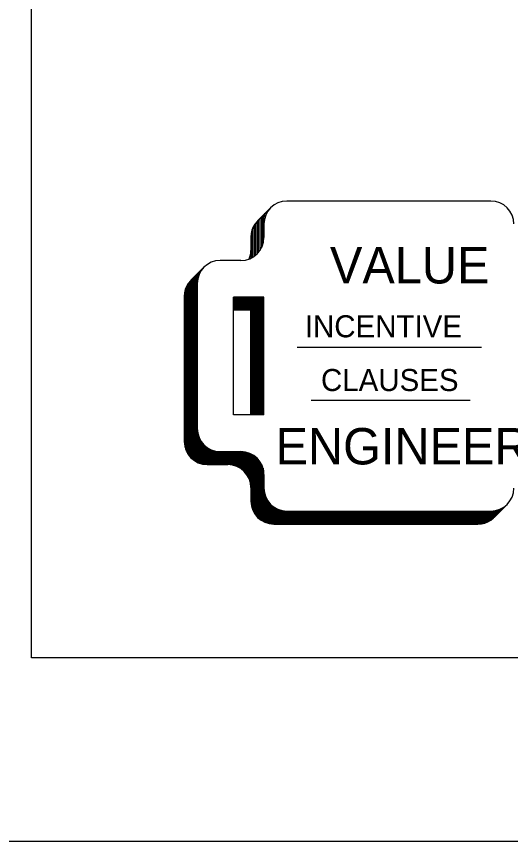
# Model space of a CAD drawing. Extents: x 0 to 53.3, y -2.9 to 37.3.
# Drawn here: x 1.943 to 3.736, y 0.002 to 2.995 of the extents above; entities that cross this region are included whole.
import ezdxf

# ---------------------------------------------------------------- set-up
doc = ezdxf.new("R2010")
doc.units = 0
doc.layers.add('Level 1', color=7, linetype='Continuous')

msp = doc.modelspace()

# ---------------------------------------------------------------- linework, layer by layer
at = {"layer": 'Level 1'}
for p, q in [((3.6651, 2.3253), (2.9244, 2.3253)), ((2.8183, 2.2538), (2.8654, 2.3009)), ((2.8411, 2.2419), (2.8411, 2.2766)), ((2.8451, 2.2674), (2.8451, 2.2806)), ((2.8494, 2.2783), (2.8494, 2.2849)), ((2.8536, 2.2858), (2.8536, 2.2891)), ((2.8571, 2.2911), (2.8571, 2.2926)), ((2.8149, 2.2501), (2.8149, 2.1321)), ((2.8204, 2.2559), (2.8204, 2.1378)), ((2.8261, 2.2616), (2.8261, 2.1451)), ((2.8321, 2.2676), (2.8321, 2.1551)), ((2.8378, 2.2733), (2.8378, 2.1694)), ((2.7984, 2.2218), (2.7984, 2.1201)), ((2.8041, 2.2346), (2.8041, 2.1234)), ((2.8093, 2.2429), (2.8093, 2.1273)), ((2.8411, 2.2419), (2.8411, 2.1928)), ((2.7939, 2.1948), (2.7939, 2.1178)), ((2.7578, 2.1094), (2.6824, 2.1094)), ((2.5763, 2.0379), (2.6234, 2.0851)), ((2.6051, 2.0571), (2.6051, 2.0668)), ((2.6068, 2.0609), (2.6068, 2.0684)), ((2.6083, 2.0641), (2.6083, 2.0699)), ((2.6099, 2.0673), (2.6099, 2.0716)), ((2.6116, 2.0699), (2.6116, 2.0733)), ((2.6133, 2.0726), (2.6133, 2.0749)), ((2.6149, 2.0749), (2.6149, 2.0766)), ((2.5743, 2.0358), (2.5743, 1.3954)), ((2.5766, 2.0381), (2.5766, 1.3931)), ((2.5794, 2.0411), (2.5794, 1.3904)), ((2.5814, 2.0431), (2.5814, 1.3886)), ((2.5836, 2.0453), (2.5836, 1.3869)), ((2.5863, 2.0479), (2.5863, 1.3849)), ((2.5891, 2.0508), (2.5891, 1.3829)), ((2.5914, 2.0531), (2.5914, 1.3814)), ((2.5936, 2.0553), (2.5936, 1.3801)), ((2.5958, 2.0574), (2.5958, 1.3789)), ((2.5973, 2.0589), (2.5973, 1.3781)), ((2.5991, 2.0261), (2.5991, 2.0608)), ((2.6009, 2.0434), (2.6009, 2.0626)), ((2.6033, 2.0521), (2.6033, 2.0649)), ((2.5568, 2.0069), (2.5568, 1.4243)), ((2.5594, 2.0134), (2.5594, 1.4178)), ((2.5616, 2.0179), (2.5616, 1.4133)), ((2.5643, 2.0226), (2.5643, 1.4086)), ((2.5669, 2.0266), (2.5669, 1.4046)), ((2.5698, 2.0304), (2.5698, 1.4008)), ((2.5721, 2.0333), (2.5721, 1.3979)), ((2.5991, 2.0261), (2.5991, 1.4994)), ((2.5519, 1.9789), (2.5519, 1.4523)), ((2.5543, 1.9984), (2.5543, 1.4328)), ((2.8411, 1.9761), (2.7308, 1.9761)), ((2.7308, 1.5494), (2.7308, 1.9761)), ((2.8411, 1.9761), (2.7939, 1.9289)), ((2.8411, 1.5494), (2.8411, 1.9761)), ((2.8411, 1.9739), (2.7308, 1.9739)), ((2.8411, 1.9718), (2.7308, 1.9718)), ((2.8411, 1.9693), (2.7308, 1.9693)), ((2.8411, 1.9668), (2.7308, 1.9668)), ((2.8411, 1.9641), (2.7308, 1.9641)), ((2.8411, 1.9616), (2.7308, 1.9616)), ((2.8411, 1.9591), (2.7308, 1.9591)), ((2.8411, 1.9564), (2.7308, 1.9564)), ((2.8411, 1.9541), (2.7308, 1.9541)), ((2.8411, 1.9516), (2.7308, 1.9516)), ((2.8411, 1.9491), (2.7308, 1.9491)), ((2.8411, 1.9468), (2.7308, 1.9468)), ((2.8411, 1.9444), (2.7308, 1.9444)), ((2.8411, 1.9424), (2.7308, 1.9424)), ((2.8411, 1.9399), (2.7308, 1.9399)), ((2.8411, 1.9379), (2.7308, 1.9379)), ((2.8411, 1.9358), (2.7308, 1.9358)), ((2.8411, 1.9338), (2.7308, 1.9338)), ((2.8411, 1.9313), (2.7308, 1.9313)), ((2.7939, 1.9289), (2.7308, 1.9289)), ((2.7939, 1.5494), (2.7939, 1.9289)), ((2.7963, 1.5494), (2.7963, 1.9313)), ((2.7981, 1.5494), (2.7981, 1.9313)), ((2.8001, 1.5494), (2.8001, 1.9313)), ((2.8018, 1.5494), (2.8018, 1.9313)), ((2.8043, 1.5494), (2.8043, 1.9313)), ((2.8064, 1.5494), (2.8064, 1.9313)), ((2.8088, 1.5494), (2.8088, 1.9313)), ((2.8104, 1.5494), (2.8104, 1.9313)), ((2.8131, 1.5494), (2.8131, 1.9313)), ((2.8153, 1.5494), (2.8153, 1.9313)), ((2.8171, 1.5494), (2.8171, 1.9313)), ((2.8193, 1.5494), (2.8193, 1.9313)), ((2.8214, 1.5494), (2.8214, 1.9313)), ((2.8239, 1.5494), (2.8239, 1.9313)), ((2.8259, 1.5494), (2.8259, 1.9313)), ((2.8279, 1.5494), (2.8279, 1.9313)), ((2.8304, 1.5494), (2.8304, 1.9313)), ((2.8329, 1.5494), (2.8329, 1.9313)), ((2.8354, 1.5494), (2.8354, 1.9313)), ((2.8371, 1.5494), (2.8371, 1.9313)), ((2.8393, 1.5494), (2.8393, 1.9313)), ((2.9619, 1.7949), (3.6311, 1.7949)), ((3.0123, 1.6029), (3.5898, 1.6029)), ((2.8411, 1.5494), (2.7308, 1.5494)), ((2.6003, 1.4856), (2.6003, 1.3766)), ((2.6029, 1.4744), (2.6029, 1.3754)), ((2.6054, 1.4676), (2.6054, 1.3744)), ((2.6079, 1.4621), (2.6079, 1.3736)), ((2.6109, 1.4566), (2.6109, 1.3726)), ((2.6131, 1.4533), (2.6131, 1.3719)), ((2.6153, 1.4501), (2.6153, 1.3714)), ((2.6181, 1.4464), (2.6181, 1.3708)), ((2.6204, 1.4438), (2.6204, 1.3703)), ((2.6229, 1.4411), (2.6229, 1.3699)), ((2.6254, 1.4386), (2.6254, 1.3694)), ((2.6279, 1.4364), (2.6279, 1.3693)), ((2.6303, 1.4344), (2.6303, 1.3691)), ((2.6331, 1.4323), (2.6331, 1.3689)), ((2.6356, 1.4304), (2.6356, 1.3689)), ((2.6381, 1.4289), (2.6381, 1.3689)), ((2.6406, 1.4274), (2.6406, 1.3689)), ((2.6436, 1.4258), (2.6436, 1.3689)), ((2.6458, 1.4246), (2.6458, 1.3689)), ((2.6471, 1.4239), (2.6471, 1.3689)), ((2.6493, 1.4229), (2.6493, 1.3689)), ((2.6514, 1.4221), (2.6514, 1.3689)), ((2.6541, 1.4211), (2.6541, 1.3689)), ((2.6568, 1.4201), (2.6568, 1.3689)), ((2.6593, 1.4194), (2.6593, 1.3689)), ((2.6626, 1.4184), (2.6626, 1.3689)), ((2.6656, 1.4178), (2.6656, 1.3689)), ((2.6681, 1.4173), (2.6681, 1.3689)), ((2.6699, 1.4171), (2.6699, 1.3689)), ((2.6724, 1.4168), (2.6724, 1.3689)), ((2.6746, 1.4164), (2.6746, 1.3689)), ((2.6764, 1.4163), (2.6764, 1.3689)), ((2.6788, 1.4161), (2.6788, 1.3689)), ((2.6814, 1.4161), (2.6814, 1.3689)), ((2.6824, 1.4161), (2.7578, 1.4161)), ((2.6839, 1.4161), (2.6839, 1.3689)), ((2.6868, 1.4161), (2.6868, 1.3689)), ((2.6896, 1.4161), (2.6896, 1.3689)), ((2.6921, 1.4161), (2.6921, 1.3689)), ((2.6954, 1.4161), (2.6954, 1.3689)), ((2.6983, 1.4161), (2.6983, 1.3689)), ((2.7008, 1.4161), (2.7008, 1.3689)), ((2.7036, 1.4161), (2.7036, 1.3689)), ((2.7068, 1.4161), (2.7068, 1.3689)), ((2.7098, 1.4161), (2.7098, 1.3689)), ((2.7129, 1.4161), (2.7129, 1.3689)), ((2.7161, 1.4161), (2.7161, 1.3689)), ((2.7198, 1.4161), (2.7198, 1.3684)), ((2.7223, 1.4161), (2.7223, 1.3681)), ((2.7244, 1.4161), (2.7244, 1.3678)), ((2.7266, 1.4161), (2.7266, 1.3674)), ((2.7301, 1.4161), (2.7301, 1.3666)), ((2.7338, 1.4161), (2.7338, 1.3656)), ((2.7376, 1.4161), (2.7376, 1.3644)), ((2.7413, 1.4161), (2.7413, 1.3631)), ((2.7444, 1.4161), (2.7444, 1.3618)), ((2.7481, 1.4161), (2.7481, 1.3601)), ((2.7509, 1.4161), (2.7509, 1.3586)), ((2.7553, 1.4161), (2.7553, 1.3559)), ((2.7588, 1.4161), (2.7588, 1.3536)), ((2.7606, 1.4161), (2.7606, 1.3523)), ((2.7638, 1.4161), (2.7638, 1.3498)), ((2.7663, 1.4156), (2.7663, 1.3476)), ((2.7689, 1.4153), (2.7689, 1.3451)), ((2.7714, 1.4149), (2.7714, 1.3426)), ((2.7733, 1.4146), (2.7733, 1.3406)), ((2.7761, 1.4141), (2.7761, 1.3371)), ((2.7789, 1.4134), (2.7789, 1.3333)), ((2.7819, 1.4126), (2.7819, 1.3286)), ((2.7848, 1.4116), (2.7848, 1.3236)), ((2.7873, 1.4108), (2.7873, 1.3183)), ((2.7899, 1.4096), (2.7899, 1.3111)), ((2.7928, 1.4084), (2.7928, 1.2994)), ((2.7949, 1.4074), (2.7949, 1.2236)), ((2.7976, 1.4059), (2.7976, 1.2119)), ((2.8003, 1.4044), (2.8003, 1.2046)), ((2.8028, 1.4029), (2.8028, 1.1991)), ((2.8053, 1.4013), (2.8053, 1.1944)), ((2.8078, 1.3994), (2.8078, 1.1904)), ((2.8106, 1.3973), (2.8106, 1.1864)), ((2.8128, 1.3954), (2.8128, 1.1836)), ((2.8153, 1.3931), (2.8153, 1.1808)), ((2.8174, 1.3909), (2.8174, 1.1784)), ((2.8201, 1.3881), (2.8201, 1.1758)), ((2.8226, 1.3851), (2.8226, 1.1736)), ((2.8254, 1.3814), (2.8254, 1.1711)), ((2.8281, 1.3774), (2.8281, 1.1691)), ((2.6353, 1.3689), (2.7106, 1.3689)), ((2.8303, 1.3739), (2.8303, 1.1676)), ((2.8323, 1.3701), (2.8323, 1.1663)), ((2.8339, 1.3666), (2.8339, 1.1653)), ((2.8361, 1.3613), (2.8361, 1.1639)), ((2.8379, 1.3556), (2.8379, 1.1629)), ((2.8394, 1.3493), (2.8394, 1.1621)), ((2.8411, 1.3328), (2.8411, 1.2836)), ((2.7939, 1.2856), (2.7939, 1.2364)), ((2.8413, 1.2783), (2.8413, 1.1613)), ((2.8436, 1.2633), (2.8436, 1.1603)), ((2.8458, 1.2561), (2.8458, 1.1593)), ((2.8476, 1.2513), (2.8476, 1.1586)), ((2.8496, 1.2469), (2.8496, 1.1578)), ((2.8513, 1.2438), (2.8513, 1.1573)), ((2.8536, 1.2398), (2.8536, 1.1566)), ((2.8558, 1.2364), (2.8558, 1.1559)), ((2.8581, 1.2331), (2.8581, 1.1553)), ((2.8598, 1.2311), (2.8598, 1.1549)), ((2.8621, 1.2283), (2.8621, 1.1544)), ((2.8634, 1.2268), (2.8634, 1.1543)), ((2.8653, 1.2249), (2.8653, 1.1539)), ((2.8673, 1.2229), (2.8673, 1.1538)), ((2.8688, 1.2216), (2.8688, 1.1536)), ((2.8698, 1.2208), (2.8698, 1.1534)), ((2.8709, 1.2198), (2.8709, 1.1533)), ((2.8728, 1.2183), (2.8728, 1.1533)), ((2.8751, 1.2164), (2.8751, 1.1533)), ((2.8778, 1.2146), (2.8778, 1.1533)), ((2.8801, 1.2131), (2.8801, 1.1533)), ((2.8828, 1.2114), (2.8828, 1.1533)), ((2.8853, 1.2101), (2.8853, 1.1533)), ((2.8878, 1.2088), (2.8878, 1.1533)), ((2.8898, 1.2078), (2.8898, 1.1533)), ((2.8921, 1.2068), (2.8921, 1.1533)), ((2.8948, 1.2058), (2.8948, 1.1533)), ((2.8974, 1.2048), (2.8974, 1.1533)), ((2.9001, 1.2039), (2.9001, 1.1533)), ((2.9029, 1.2031), (2.9029, 1.1533)), ((2.9059, 1.2023), (2.9059, 1.1533)), ((2.9083, 1.2018), (2.9083, 1.1533)), ((2.9113, 1.2013), (2.9113, 1.1533)), ((2.9139, 1.2009), (2.9139, 1.1533)), ((2.9166, 1.2006), (2.9166, 1.1533)), ((2.9198, 1.2004), (2.9198, 1.1533)), ((2.9224, 1.2003), (2.9224, 1.1533)), ((2.9224, 1.1991), (3.6179, 1.1991)), ((2.9224, 1.1983), (3.6179, 1.1983)), ((2.9224, 1.1974), (3.6179, 1.1974)), ((2.9244, 1.2003), (3.6651, 1.2003)), ((3.6179, 1.1531), (3.6179, 1.2003)), ((3.6198, 1.1531), (3.6198, 1.2003)), ((3.6211, 1.1531), (3.6211, 1.2003)), ((3.6224, 1.1533), (3.6224, 1.2003)), ((3.6246, 1.1534), (3.6246, 1.2003)), ((3.6263, 1.1536), (3.6263, 1.2003)), ((3.6283, 1.1538), (3.6283, 1.2003)), ((3.6299, 1.1539), (3.6299, 1.2003)), ((3.6318, 1.1543), (3.6318, 1.2003)), ((3.6333, 1.1546), (3.6333, 1.2003)), ((3.6353, 1.1549), (3.6353, 1.2003)), ((3.6371, 1.1553), (3.6371, 1.2003)), ((3.6389, 1.1558), (3.6389, 1.2003)), ((3.6413, 1.1564), (3.6413, 1.2003)), ((3.6438, 1.1573), (3.6438, 1.2003)), ((3.6458, 1.1579), (3.6458, 1.2003)), ((3.6478, 1.1586), (3.6478, 1.2003)), ((3.6499, 1.1594), (3.6499, 1.2003)), ((3.6521, 1.1604), (3.6521, 1.2003)), ((3.6539, 1.1613), (3.6539, 1.2003)), ((3.6564, 1.1626), (3.6564, 1.2003)), ((3.6589, 1.1639), (3.6589, 1.2003)), ((3.6613, 1.1653), (3.6613, 1.2003)), ((3.6636, 1.1668), (3.6636, 1.2003)), ((3.6659, 1.1683), (3.6659, 1.2003)), ((3.6681, 1.1699), (3.6681, 1.2003)), ((3.6704, 1.1718), (3.6704, 1.2003)), ((3.6729, 1.1738), (3.6729, 1.2006)), ((3.6753, 1.1759), (3.6753, 1.2009)), ((3.6769, 1.1774), (3.7241, 1.2246)), ((3.6773, 1.1778), (3.6773, 1.2011)), ((3.6794, 1.1799), (3.6794, 1.2014)), ((3.6811, 1.1816), (3.6811, 1.2018)), ((3.6831, 1.1836), (3.6831, 1.2023)), ((3.6848, 1.1853), (3.6848, 1.2026)), ((3.6866, 1.1871), (3.6866, 1.2031)), ((3.6886, 1.1891), (3.6886, 1.2036)), ((3.6899, 1.1904), (3.6899, 1.2041)), ((3.6916, 1.1921), (3.6916, 1.2046)), ((3.6931, 1.1936), (3.6931, 1.2051)), ((3.6948, 1.1953), (3.6948, 1.2058)), ((3.6958, 1.1963), (3.6958, 1.2061)), ((3.6978, 1.1983), (3.6978, 1.2069)), ((3.6993, 1.1998), (3.6993, 1.2076)), ((3.7009, 1.2014), (3.7009, 1.2084)), ((3.7028, 1.2033), (3.7028, 1.2093)), ((3.7043, 1.2048), (3.7043, 1.2101)), ((3.7058, 1.2063), (3.7058, 1.2109)), ((3.7073, 1.2078), (3.7073, 1.2118)), ((3.7089, 1.2094), (3.7089, 1.2128)), ((3.7106, 1.2111), (3.7106, 1.2138)), ((3.7121, 1.2126), (3.7121, 1.2148)), ((3.7136, 1.2141), (3.7136, 1.2158)), ((3.7151, 1.2156), (3.7151, 1.2169)), ((2.9224, 1.1963), (3.6179, 1.1963)), ((2.9224, 1.1949), (3.6179, 1.1949)), ((2.9224, 1.1934), (3.6179, 1.1934)), ((2.9224, 1.1919), (3.6179, 1.1919)), ((2.9224, 1.1906), (3.6179, 1.1906)), ((2.9224, 1.1891), (3.6179, 1.1891)), ((2.9224, 1.1876), (3.6179, 1.1876)), ((2.9224, 1.1861), (3.6179, 1.1861)), ((2.9224, 1.1846), (3.6179, 1.1846)), ((2.9224, 1.1831), (3.6179, 1.1831)), ((2.9224, 1.1818), (3.6179, 1.1818)), ((2.9224, 1.1803), (3.6179, 1.1803)), ((2.9224, 1.1789), (3.6179, 1.1789)), ((2.9224, 1.1776), (3.6179, 1.1776)), ((2.9224, 1.1761), (3.6179, 1.1761)), ((2.9224, 1.1746), (3.6179, 1.1746)), ((2.9224, 1.1729), (3.6179, 1.1729)), ((2.9224, 1.1713), (3.6179, 1.1713)), ((2.9224, 1.1696), (3.6179, 1.1696)), ((2.9224, 1.1681), (3.6179, 1.1681)), ((2.8773, 1.1531), (3.6179, 1.1531)), ((2.9224, 1.1663), (3.6179, 1.1663)), ((2.9224, 1.1646), (3.6179, 1.1646)), ((2.9224, 1.1628), (3.6179, 1.1628)), ((2.9224, 1.1609), (3.6179, 1.1609)), ((2.9224, 1.1589), (3.6179, 1.1589)), ((2.9224, 1.1571), (3.6179, 1.1571)), ((2.9224, 1.1553), (3.6179, 1.1553))]:
    msp.add_line(p, q, dxfattribs=at)
for points in [[(-0.0026, 37.3348), (53.3308, 37.3348), (53.3308, 0.0015), (-0.0026, 0.0015)], [(1.9974, 36.6682), (52.6641, 36.6682), (52.6641, 0.6682), (1.9974, 0.6682)]]:
    msp.add_lwpolyline(points, close=True, dxfattribs=at)
for centre, start, end in [((2.9244, 2.2419), 90, 180), ((3.6651, 2.2419), 0, 90), ((2.8773, 2.1948), 111.4079, 180), ((2.7578, 2.1928), 270, 0), ((2.7106, 2.1456), 338.5921, 0), ((2.6824, 2.0261), 90, 180), ((2.6353, 1.9789), 111.4079, 180), ((2.6824, 1.4994), 180, 270), ((2.6353, 1.4523), 180, 270), ((2.7578, 1.3328), 0, 90), ((2.7106, 1.2856), 0, 90), ((2.9244, 1.2836), 180, 270), ((3.6651, 1.2836), 270, 0), ((2.8773, 1.2364), 180, 270), ((3.6179, 1.2364), 270, 338.5921)]:
    msp.add_arc(centre, 0.0833, start, end, dxfattribs=at)

# ---------------------------------------------------------------- texts
for s, height, p in [('VALUE', 0.13199, (3.0809, 2.0261)), ('INCENTIVE', 0.08, (2.9896, 1.8308)), ('CLAUSES', 0.08, (3.0483, 1.6358)), ('ENGINEERING', 0.13199, (2.8833, 1.3696))]:
    msp.add_text(s, height=height, dxfattribs=at).set_placement(p)

doc.saveas('drawing.dxf')
